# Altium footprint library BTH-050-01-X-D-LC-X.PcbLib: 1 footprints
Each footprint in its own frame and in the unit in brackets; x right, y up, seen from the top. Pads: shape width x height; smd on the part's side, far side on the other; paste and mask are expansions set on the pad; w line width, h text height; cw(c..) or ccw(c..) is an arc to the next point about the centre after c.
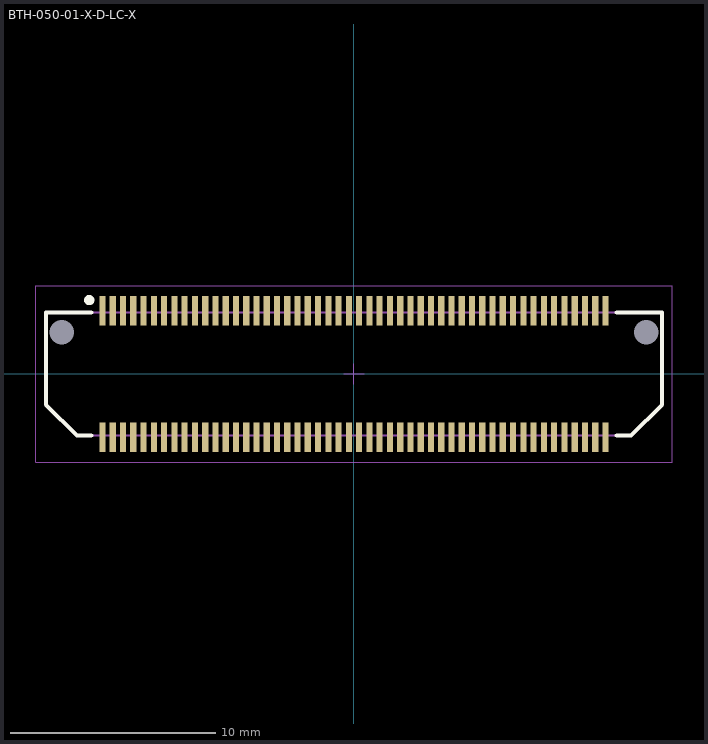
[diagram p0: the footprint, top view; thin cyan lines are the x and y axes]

## BTH-050-01-X-D-LC-X [mm] "0.50mm pitch, 100 pin, terminal strip; w/locking clips"
height 4.27
pads (102):
  rect 0.3x1.45 smd mask+0: 1(-12.25,3.086) 2(-12.25,-3.086) 3(-11.75,3.086) 4(-11.75,-3.086) 5(-11.25,3.086) 6(-11.25,-3.086) 7(-10.75,3.086) 8(-10.75,-3.086) 9(-10.25,3.086) 10(-10.25,-3.086) 11(-9.75,3.086) 12(-9.75,-3.086) 13(-9.25,3.086) 14(-9.25,-3.086) 15(-8.75,3.086) 16(-8.75,-3.086) 17(-8.25,3.086) 18(-8.25,-3.086) 19(-7.75,3.086) 20(-7.75,-3.086) 21(-7.25,3.086) 22(-7.25,-3.086) 23(-6.75,3.086) 24(-6.75,-3.086) 25(-6.25,3.086) 26(-6.25,-3.086) 27(-5.75,3.086) 28(-5.75,-3.086) 29(-5.25,3.086) 30(-5.25,-3.086) 31(-4.75,3.086) 32(-4.75,-3.086) 33(-4.25,3.086) 34(-4.25,-3.086) 35(-3.75,3.086) 36(-3.75,-3.086) 37(-3.25,3.086) 38(-3.25,-3.086) 39(-2.75,3.086) 40(-2.75,-3.086) 41(-2.25,3.086) 42(-2.25,-3.086) 43(-1.75,3.086) 44(-1.75,-3.086) 45(-1.25,3.086) 46(-1.25,-3.086) 47(-0.75,3.086) 48(-0.75,-3.086) 49(-0.25,3.086) 50(-0.25,-3.086) 51(0.25,3.086) 52(0.25,-3.086) 53(0.75,3.086) 54(0.75,-3.086) 55(1.25,3.086) 56(1.25,-3.086) 57(1.75,3.086) 58(1.75,-3.086) 59(2.25,3.086) 60(2.25,-3.086) 61(2.75,3.086) 62(2.75,-3.086) 63(3.25,3.086) 64(3.25,-3.086) 65(3.75,3.086) 66(3.75,-3.086) 67(4.25,3.086) 68(4.25,-3.086) 69(4.75,3.086) 70(4.75,-3.086) 71(5.25,3.086) 72(5.25,-3.086) 73(5.75,3.086) 74(5.75,-3.086) 75(6.25,3.086) 76(6.25,-3.086) 77(6.75,3.086) 78(6.75,-3.086) 79(7.25,3.086) 80(7.25,-3.086) 81(7.75,3.086) 82(7.75,-3.086) 83(8.25,3.086) 84(8.25,-3.086) 85(8.75,3.086) 86(8.75,-3.086) 87(9.25,3.086) 88(9.25,-3.086) 89(9.75,3.086) 90(9.75,-3.086) 91(10.25,3.086) 92(10.25,-3.086) 93(10.75,3.086) 94(10.75,-3.086) 95(11.25,3.086) 96(11.25,-3.086) 97(11.75,3.086) 98(11.75,-3.086) 99(12.25,3.086) 100(12.25,-3.086)
  round 0.5 hole 1.2 unplated mask+0: 101(-14.237,2.032) 102(14.237,2.032)
Top Overlay:
  circle w0.25: c-12.9,3.6 r0.125
  lines w0.2: -12.8,-3 -13.5,-3 -15,-1.5 -15,3 -12.8,3 ; 12.8,-3 13.5,-3 15,-1.5 15,3 12.8,3
Mechanical 12:
  lines w0.001: -15,-1.5 -15,3 15,3 15,-1.5 13.5,-3 -13.5,-3 -15,-1.5
Mechanical 13:
  lines w0.1: -15,-1.5 -15,3 15,3 15,-1.5 13.5,-3 -13.5,-3 -15,-1.5
  text ".Designator" at 0.254,0.254 h1.52
Mechanical 15:
  lines w0.05: -0.5,0 0.5,0 ; 0,-0.5 0,0.5 ; -15.5,-4.3 -15.5,4.3 15.5,4.3 15.5,-4.3 -15.5,-4.3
